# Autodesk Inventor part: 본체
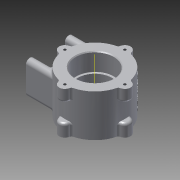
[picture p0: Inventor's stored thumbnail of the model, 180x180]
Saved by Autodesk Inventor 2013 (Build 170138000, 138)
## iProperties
Created: 2015-03
Part Number: 본체
Material: 알루미늄 6061
Document SubType Name: Modeling
Designer: cad10
Density: 2.40731 g/cm^3
Mass: 399.958 g
Surface Area: 333.879 cm^2
Volume: 166.143 cm^3
Author: cad10
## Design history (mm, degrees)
sketch "스케치1"
  geometry: C1 r 37 at (0, 0); 1 further point
  constraints: 1 centre point, 1 coincident
  dimensions: "d0" = 74 diameter of C1
extrude "돌출1" new body sketch "스케치1" distance "d2" = 52; taper "d3" = 0 deg
sketch "스케치2"
  geometry: A1 r 7 centre (0, 37) between (6.969, 36.338) and (-6.969, 36.338); A2 r 7 centre (37, 0) between (36.338, -6.969) and (36.338, 6.969); A3 r 7 centre (0, -37) between (-6.969, -36.338) and (6.969, -36.338); A4 r 7 centre (-37, 0) between (-36.338, 6.969) and (-36.338, -6.969); 1 further point
  constraints: 8 point on circle, 4 centre point, 13 other
  dimensions: "d4" = 14 diameter of A4; "d6" = 14 diameter of A3; "d7" = 14 diameter of A2; "d8" = 14 diameter of A1
extrude "돌출2" join sketch "스케치2" distance "d9" = 15; taper "d10" = 0 deg
sketch "스케치4"
  geometry: A1 r 7 centre (0, 37) between (6.969, 36.338) and (-6.969, 36.338); A2 r 7 centre (0, -37) between (-6.969, -36.338) and (6.969, -36.338); A3 r 7 centre (-37, 0) between (-36.338, 6.969) and (-36.338, -6.969); A4 r 7 centre (37, 0) between (36.338, -6.969) and (36.338, 6.969); 1 further point
  constraints: 8 point on circle, 4 centre point, 13 other
  dimensions: "d14" = 14 diameter of A1; "d15" = 14 diameter of A2; "d16" = 14 diameter of A3; "d17" = 14 diameter of A4
extrude "돌출3" join sketch "스케치4" distance "d18" = 15; taper "d19" = 0 deg
sketch "스케치5"
  geometry: C1 r 23.5 at (0, 0); A1 r 37 centre (0, 0) between (-6.969, 36.338) and (-36.338, 6.969) reference
  constraints: 1 centre point, 1 coincident
  dimensions: "d20" = 47 diameter of C1
extrude "돌출4" cut sketch "스케치5" distance "d22" = 22; taper "d23" = 0 deg
sketch "스케치6"
  geometry: C1 r 23.5 at (0, 0) reference; C2 r 21 at (0, 0)
  constraints: 1 centre point, 1 coincident
  dimensions: "d24" = 42 diameter of C2
extrude "돌출5" cut sketch "스케치6" distance "d26" = 18; taper "d27" = 0 deg
sketch "스케치7"
  geometry: C1 r 23.5 at (0, 0); A1 r 37 centre (0, 0) between (6.969, -36.338) and (36.338, -6.969) reference
  constraints: 1 centre point, 1 coincident
  dimensions: "d28" = 47 diameter of C1
extrude "돌출6" cut sketch "스케치7" distance "d31" = 22; taper "d32" = 0 deg
node "작업 평면1"
sketch "스케치8"
  geometry: L1 (-29, 11)-(-29, 41); L2 (-19, 11)-(-19, 41); L3 (19, 41)-(19, 33.05); L4 (19, 33.05)-(19, 11); L5 (29, 41)-(29, 11); A1 r 5 centre (-24, 41) between (-19, 41) and (-29, 41); A2 r 5 centre (-24, 11) between (-29, 11) and (-19, 11); A3 r 5 centre (24, 41) between (29, 41) and (19, 41); A4 r 5 centre (24, 11) between (19, 11) and (29, 11)
  constraints: 10 end point, 8 point on circle, 5 tangent, 4 centre point, 1 parallel
  dimensions: "d85" = 30 distance of A2.centre A1.centre; "d88" = 30 distance of A3.centre A4.centre
extrude "돌출7" join sketch "스케치8" distance "d40" = 35; taper "d41" = 0 deg
sketch "스케치10"
  geometry: A1 r 7 centre (0, 37) between (6.969, 36.338) and (-6.969, 36.338) reference; A2 r 7 centre (-37, 0) between (-36.338, 6.969) and (-36.338, -6.969) reference; A3 r 7 centre (0, -37) between (-6.969, -36.338) and (6.969, -36.338) reference; A4 r 7 centre (37, 0) between (36.338, -6.969) and (36.338, 6.969) reference
hole "구멍1" sketch "스케치10" at (37, 0), (0, 37), (-37, 0), (0, -37) diameter "d42" = 3.242; stored, may be unused: countersink angle "d46" = 90 deg, drill point angle "d48" = 118 deg; dims "d43" = 8, "d44" = 4, "d45" = 2, "d47" = 11
sketch "스케치11"
  geometry: A1 r 7 centre (0, -37) between (-6.969, -36.338) and (6.969, -36.338) reference; A2 r 7 centre (37, 0) between (36.338, -6.969) and (36.338, 6.969) reference; A3 r 7 centre (0, 37) between (6.969, 36.338) and (-6.969, 36.338) reference; A4 r 7 centre (-37, 0) between (-36.338, 6.969) and (-36.338, -6.969) reference
hole "구멍2" sketch "스케치11" at (-37, 0), (0, -37), (37, 0), (0, 37) diameter "d49" = 3.242; stored, may be unused: countersink angle "d53" = 90 deg, drill point angle "d55" = 118 deg; dims "d50" = 8, "d51" = 4, "d52" = 2, "d54" = 11
sketch "스케치12"
  geometry: A1 r 5 centre (11, -24) between (11, -19) and (11, -29) reference; A2 r 5 centre (41, -24) between (41, -29) and (41, -19) reference; 1 further point
hole "구멍3" sketch "스케치12" at (11, -24), (41, -24) diameter "d56" = 4.134; stored, may be unused: countersink angle "d60" = 90 deg, drill point angle "d62" = 118 deg; dims "d57" = 6, "d58" = 4, "d59" = 2, "d61" = 8
sketch "스케치13"
  geometry: A1 r 5 centre (41, 24) between (41, 19) and (41, 29) reference; A2 r 5 centre (11, 24) between (11, 29) and (11, 19) reference; 1 further point
hole "구멍4" sketch "스케치13" at (11, 24), (41, 24) diameter "d63" = 4.134; stored, may be unused: countersink angle "d67" = 90 deg, drill point angle "d69" = 118 deg; dims "d64" = 6, "d65" = 4, "d66" = 2, "d68" = 8
fillet "모깎기1" dims "d70" = 3
fillet "모깎기2" dims "d71" = 3
fillet "모깎기3" dims "d72" = 3
chamfer "모따기1" distance "d73" = 1; stored, may be unused: second distance "d74" = 2, angle "d75" = 45 deg
chamfer "모따기2" distance "d76" = 1; stored, may be unused: second distance "d77" = 2, angle "d78" = 45 deg
fillet "모깎기4" dims "d79" = 0.3
node "작업 평면3"
  node "작업 평면2"
sketch "스케치14"
  geometry: 2 further points
  constraints: 1 other
feature "엠보싱1" sketch "스케치14" dims "d14" = 14, "d90" = 0.5, "d91" = 0
node "솔리드1"
node "작업축1"
other parameters: "d33" = -56, "d34" = 24, "d36" = 5, "d37" = 5, "d38" = 15, "d39" = 15, "d80" = 45 deg, "d81" = 78.75
